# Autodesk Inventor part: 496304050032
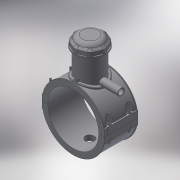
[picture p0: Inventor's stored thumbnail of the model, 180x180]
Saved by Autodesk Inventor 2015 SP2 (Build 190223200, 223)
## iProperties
Created: 2017-07
Part Number: 496304050032
Material: Generic
Description: PLASSON TAPPING SADDLE 50x32
Document SubType Name: Modeling
Designer: KIM
Mass: 185.958 g
Surface Area: 794.676 cm^2
Volume: 185.958 cm^3
Density: 1 g/cm^3
Appearance: Default
Author: KIM
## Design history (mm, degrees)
derived "496304.ipt"
feature "Solid1::496304.ipt"
feature "Solid2::496304.ipt"
feature "Solid4::496304.ipt"
feature "Solid5::496304.ipt"
tag "TaggingFeature1"
body "Solid1"
body "Solid2"
other parameters: "B_" = 76, "d_t" = 6, "H_2" = 98, "H_1" = 12, "d_1" = 32, "H_" = 122, "d1" = 65, "d148" = 0.75, "d160" = 0.75, "d169" = 3.375, "d192" = 6.3, "d2" = 76, "d3" = 12.5, "d5" = 0, "d6" = 0.1, "d8" = 0, "d19" = 6, "d20" = 6, "d23" = 0, "d26" = 0, "d29" = 3, "d30" = 16.66667, "d31" = 6, "d32" = 0, "d33" = 0, "d34" = 0.6, "d40" = 33.8, "d41" = 45, "d43" = 0, "d45" = 0, "d47" = 92.5, "d70" = 15, "d72" = 0, "d73" = 6, "d75" = 5, "d76" = 0, "d77" = 2.5, "d78" = 55, "d79" = 15, "d82" = 5 deg, "d84" = 4, "d85" = 14, "d86" = 0, "d87" = 3, "d88" = 0, "d89" = 1, "d90" = 1, "d92" = 0, "d93" = 0.5, "d94" = 26.31579, "d96" = 66.3, "d97" = 2, "d98" = 0, "d102" = 0.5, "d120" = 140 deg, "d121" = 24.228, "d122" = 20 deg, "d124" = 39, "d126" = 0, "d143" = 51.5, "d145" = 11.53846, "d149" = 0.75, "d150" = 12.69231, "d154" = 0, "d156" = 32.5, "d157" = 160 deg, "d159" = 3, "d161" = 0.75, "d163" = 0, "d164" = 25, "d167" = 5, "d168" = 31.70732, "d170" = 3.375, "d172" = 0, "d173" = 1, "d175" = 25, "d176" = 20 deg, "d177" = 3.5, "d178" = 15, "d180" = 0, "d183" = 6, "d184" = 2.8, "d185" = 32.5, "d186" = 32.5, "d187" = 32.5, "d188" = 4.5, "d189" = 3.5, "d190" = 0, "d191" = 48.75, "d193" = 6.3, "d194" = 3.5, "d195" = 90 deg, "d197" = 0, "d199" = 0, "d200" = 7.5, "d202" = 0, "d203" = 98, "d204" = 42.75, "d205" = 31.5, "d206" = 38.25, "d207" = 73.5, "d208" = 76.44, "d209" = 91.14, "d210" = 38.7, "d211" = 45, "d212" = 36, "d213" = -3.6, "d216" = 0, "d217" = 5, "d218" = 5, "d219" = 1, "d224" = 0, "d230" = 3, "d233" = 6, "d236" = 38, "d238" = 6.02433, "d243" = 6, "d247" = 6, "d248" = 6, "d249" = 6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
